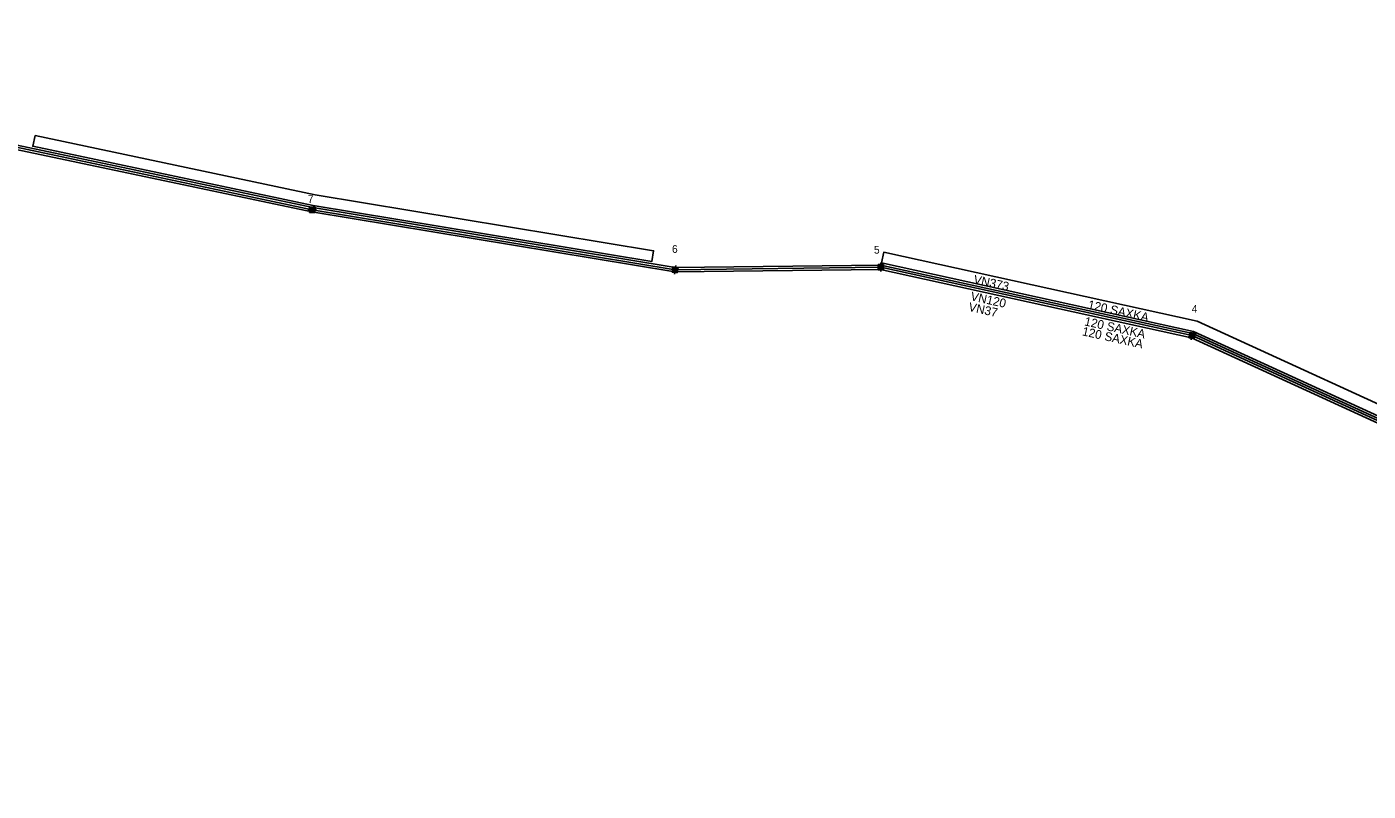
# Model space of a CAD drawing. Extents: x -540340 to -537226, y -1183949 to -1180375.
# Drawn here: x -537965.2 to -537658.9, y -1180650.1 to -1180475.4 of the extents above; entities that cross this region are included whole.
import ezdxf

# ---------------------------------------------------------------- set-up
doc = ezdxf.new("R2010")
doc.units = 0
for name, color, linetype in [('Vrstva 13', 7, 'Continuous'), ('Vrstva 14', 7, 'Continuous'), ('Vrstva 35', 7, 'Continuous'), ('Vrstva 50', 7, 'Continuous'), ('Vrstva 51', 7, 'Continuous')]:
    doc.layers.add(name, color=color, linetype=linetype)

msp = doc.modelspace()

# ---------------------------------------------------------------- linework, layer by layer
at = {"layer": 'Vrstva 13'}
for points in [[(-537900.61, -1180517.19), (-537900.99, -1180517.18)], [(-537900.62, -1180517.8), (-537900.6, -1180516.57)], [(-537900.6, -1180516.57), (-537899.37, -1180516.6)], [(-537900.46, -1180517.65), (-537900.44, -1180516.73)], [(-537900.44, -1180516.73), (-537899.52, -1180516.75)], [(-537900.31, -1180517.5), (-537900.3, -1180516.89)], [(-537899.7, -1180517.51), (-537900.31, -1180517.5)], [(-537900.3, -1180516.89), (-537899.68, -1180516.9)], [(-537900.17, -1180517.04), (-537899.86, -1180517.05)], [(-537900.17, -1180517.35), (-537900.17, -1180517.04)], [(-537899.87, -1180517.36), (-537900.17, -1180517.35)], [(-537899.86, -1180517.05), (-537899.87, -1180517.36)], [(-537899.68, -1180516.9), (-537899.7, -1180517.51)], [(-537899.52, -1180516.75), (-537899.54, -1180517.67)], [(-537899.37, -1180516.6), (-537899.4, -1180517.83)], [(-537899.38, -1180517.21), (-537899.01, -1180517.22)], [(-537899.4, -1180517.83), (-537900.62, -1180517.8)], [(-537899.54, -1180517.67), (-537900.46, -1180517.65)], [(-537770.79, -1180529.73), (-537769.56, -1180529.73)], [(-537770.79, -1180530.96), (-537770.79, -1180529.73)], [(-537770.17, -1180529.73), (-537770.17, -1180529.36)], [(-537769.56, -1180529.73), (-537769.56, -1180530.96)], [(-537817.84, -1180531.42), (-537817.64, -1180530.21)], [(-537816.63, -1180531.62), (-537817.84, -1180531.42)], [(-537817.66, -1180531.3), (-537817.51, -1180530.4)], [(-537816.75, -1180531.46), (-537817.66, -1180531.3)], [(-537817.64, -1180530.21), (-537816.42, -1180530.41)], [(-537817.51, -1180530.4), (-537816.6, -1180530.55)], [(-537817.48, -1180531.17), (-537817.38, -1180530.56)], [(-537816.88, -1180531.27), (-537817.48, -1180531.17)], [(-537817.38, -1180530.56), (-537816.78, -1180530.66)], [(-537817.3, -1180531.02), (-537817.25, -1180530.72)], [(-537817, -1180531.07), (-537817.3, -1180531.02)], [(-537817.23, -1180531.52), (-537817.29, -1180531.89)], [(-537817.25, -1180530.72), (-537816.95, -1180530.77)], [(-537817.03, -1180530.31), (-537816.97, -1180529.94)], [(-537816.95, -1180530.77), (-537817, -1180531.07)], [(-537816.78, -1180530.66), (-537816.88, -1180531.27)], [(-537816.6, -1180530.55), (-537816.75, -1180531.46)], [(-537816.42, -1180530.41), (-537816.63, -1180531.62)], [(-537769.56, -1180530.96), (-537770.79, -1180530.96)], [(-537770.63, -1180529.9), (-537769.71, -1180529.9)], [(-537770.63, -1180530.82), (-537770.63, -1180529.9)], [(-537769.71, -1180530.82), (-537770.63, -1180530.82)], [(-537770.48, -1180530.04), (-537769.86, -1180530.04)], [(-537770.48, -1180530.66), (-537770.48, -1180530.04)], [(-537769.86, -1180530.66), (-537770.48, -1180530.66)], [(-537770.32, -1180530.48), (-537770.32, -1180530.18)], [(-537770.32, -1180530.18), (-537770.02, -1180530.18)], [(-537770.02, -1180530.48), (-537770.32, -1180530.48)], [(-537770.17, -1180530.96), (-537770.17, -1180531.34)], [(-537770.02, -1180530.18), (-537770.02, -1180530.48)], [(-537769.86, -1180530.04), (-537769.86, -1180530.66)], [(-537769.71, -1180529.9), (-537769.71, -1180530.82)], [(-537698.92, -1180545.37), (-537698.84, -1180545)], [(-537699.78, -1180546.43), (-537699.52, -1180545.23)], [(-537698.58, -1180546.7), (-537699.78, -1180546.43)], [(-537699.6, -1180546.33), (-537699.4, -1180545.43)], [(-537698.7, -1180546.52), (-537699.6, -1180546.33)], [(-537699.52, -1180545.23), (-537698.32, -1180545.5)], [(-537699.41, -1180546.2), (-537699.28, -1180545.6)], [(-537698.81, -1180546.33), (-537699.41, -1180546.2)], [(-537699.4, -1180545.43), (-537698.5, -1180545.62)], [(-537699.28, -1180545.6), (-537698.68, -1180545.73)], [(-537699.18, -1180546.57), (-537699.26, -1180546.93)], [(-537699.23, -1180546.06), (-537699.16, -1180545.76)], [(-537698.93, -1180546.13), (-537699.23, -1180546.06)], [(-537699.16, -1180545.76), (-537698.86, -1180545.83)], [(-537698.86, -1180545.83), (-537698.93, -1180546.13)], [(-537698.68, -1180545.73), (-537698.81, -1180546.33)], [(-537698.5, -1180545.62), (-537698.7, -1180546.52)], [(-537698.32, -1180545.5), (-537698.58, -1180546.7)]]:
    msp.add_lwpolyline(points, dxfattribs=at)
at = {"layer": 'Vrstva 35'}
for points in [[(-537963.32, -1180500.24), (-537899.35, -1180513.76), (-537822.06, -1180526.55), (-537822.46, -1180529.02), (-537899.81, -1180516.22), (-537963.83, -1180502.68)], [(-537586.56, -1180616.48), (-537594.5, -1180609.88), (-537640.39, -1180571.76), (-537698.73, -1180545.01), (-537770.01, -1180529.36), (-537769.48, -1180526.92), (-537697.93, -1180542.63), (-537639.05, -1180569.62), (-537592.91, -1180607.96), (-537584.96, -1180614.55)]]:
    msp.add_lwpolyline(points, close=True, dxfattribs=at)
at = {"layer": 'Vrstva 50'}
for points in [[(-537549.42, -1180647.98), (-537594.82, -1180610.26), (-537640.66, -1180572.18), (-537698.89, -1180545.49), (-537770.12, -1180529.84), (-537817.09, -1180530.41), (-537899.91, -1180516.71), (-537967.43, -1180502.43), (-538028.9, -1180486.5), (-538083.27, -1180475.39)], [(-537548.92, -1180649.05), (-537595.14, -1180610.65), (-537640.93, -1180572.61), (-537699.05, -1180545.96), (-537770.17, -1180530.35), (-537817.13, -1180530.91), (-537900, -1180517.2), (-537967.54, -1180502.92), (-538029.01, -1180486.99), (-538083.27, -1180475.98)], [(-537548.49, -1180650.05), (-537595.46, -1180611.03), (-537641.2, -1180573.04), (-537699.21, -1180546.44), (-537770.22, -1180530.85), (-537817.17, -1180531.41), (-537900.09, -1180517.69), (-537967.65, -1180503.41), (-538029.12, -1180487.48), (-538083.26, -1180476.62)]]:
    msp.add_lwpolyline(points, dxfattribs=at)

# ---------------------------------------------------------------- texts
at = {"layer": 'Vrstva 14'}
for s, p in [('7', (-537901.03, -1180515.62)), ('6', (-537817.85, -1180527.04)), ('5', (-537771.73, -1180527.22)), ('4', (-537699.16, -1180540.73))]:
    msp.add_text(s, height=1.75, dxfattribs=at).set_placement(p)
at = {"layer": 'Vrstva 51'}
for s, p in [('VN373', (-537749.12, -1180534.01)), ('VN120', (-537749.79, -1180537.86)), ('VN37', (-537750.26, -1180540.29)), ('120 SAXKA', (-537723, -1180539.78)), ('120 SAXKA', (-537723.79, -1180543.59)), ('120 SAXKA', (-537724.3, -1180545.87))]:
    msp.add_text(s, height=2, rotation=347.615, dxfattribs=at).set_placement(p)

doc.saveas('drawing.dxf')
